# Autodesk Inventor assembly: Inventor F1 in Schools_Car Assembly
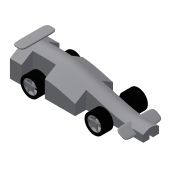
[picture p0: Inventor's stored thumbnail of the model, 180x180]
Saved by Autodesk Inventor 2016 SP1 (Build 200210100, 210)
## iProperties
Category: F1 in Schools
Company: Autodesk Inc.
Created: 2015-12
Part Number: Inventor F1 in Schools_Car Assembly
Document SubType Name: Assembly
Designer: Autodesk Inc.
Author: Autodesk Inc
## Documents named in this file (7)
- D:\F1 2016\F1 Inventor Tutorial\Data Sets\Beginner Do not Edit\Inventor F1 in Schools_CarAssembly.iam
- D:\F1 2016\F1 Inventor Tutorial\Data Sets\Beginner Do not Edit\Inventor F1 in Schools_Wheel.iam
- D:\F1 2016\F1 Inventor Tutorial\Data Sets\Beginner Do not Edit\Inventor F1 in Schools_Axle.ipt
- D:\F1 2016\F1 Inventor Tutorial\Data Sets\Beginner Do not Edit\Inventor F1 in Schools_TestBlock.ipt
- D:\F1 2016\F1 Inventor Tutorial\Data Sets\Beginner Do not Edit\Inventor F1 in Schools_RearWing.ipt
- D:\F1 2016\F1 Inventor Tutorial\Data Sets\Beginner Do not Edit\Inventor F1 in Schools_FrontWing.ipt
- D:\F1 2016\F1 Inventor Tutorial\Data Sets\Beginner Do not Edit\Inventor F1 in Schools_Body.ipt
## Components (10 placed, 6 different names)
1. Inventor F1 in Schools_Body:1 — Flush:1, Flush:2, Flush:3, Mate:1, Flush:4, Mate:2, Flush:5, Mate:4, Flush:7, Mate:7, Flush:10, Flush:11, Mate:9, Flush:12
2. Inventor F1 in Schools_RearWing:1 — Flush:1, Flush:2
3. Inventor F1 in Schools_FrontWing:1 — Flush:3
4. Inventor F1 in Schools_Wheel:1 [sub-assembly] — Mate:5, Flush:7
5. Inventor F1 in Schools_Wheel:2 [sub-assembly] — Mate:3, Mate:4
6. Inventor F1 in Schools_Wheel:3 [sub-assembly] — Mate:8, Flush:10
7. Inventor F1 in Schools_Wheel:4 [sub-assembly] — Mate:6, Mate:7
8. Inventor F1 in Schools_Axle:1 — Mate:1, Flush:4, Mate:3, Mate:5
9. Inventor F1 in Schools_Axle:2 — Mate:2, Flush:5, Mate:6, Mate:8
10. Inventor F1 in Schools_TestBlock — Flush:11, Mate:9, Flush:12
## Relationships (18: Flush 9, Mate 9)
- Flush:1: Inventor F1 in Schools_Body:1 ↔ Inventor F1 in Schools_RearWing:1
- Flush:2: Inventor F1 in Schools_Body:1 ↔ Inventor F1 in Schools_RearWing:1
- Flush:3: Inventor F1 in Schools_Body:1 ↔ Inventor F1 in Schools_FrontWing:1
- Mate:1: Inventor F1 in Schools_Body:1 ↔ Inventor F1 in Schools_Axle:1
- Flush:4: Inventor F1 in Schools_Body:1 ↔ Inventor F1 in Schools_Axle:1
- Mate:2: Inventor F1 in Schools_Body:1 ↔ Inventor F1 in Schools_Axle:2
- Flush:5: Inventor F1 in Schools_Body:1 ↔ Inventor F1 in Schools_Axle:2
- Mate:3: Inventor F1 in Schools_Wheel:2 ↔ Inventor F1 in Schools_Axle:1
- Mate:4: Inventor F1 in Schools_Body:1 ↔ Inventor F1 in Schools_Wheel:2
- Mate:5: Inventor F1 in Schools_Wheel:1 ↔ Inventor F1 in Schools_Axle:1
- Flush:7: Inventor F1 in Schools_Body:1 ↔ Inventor F1 in Schools_Wheel:1
- Mate:6: Inventor F1 in Schools_Wheel:4 ↔ Inventor F1 in Schools_Axle:2
- Mate:7: Inventor F1 in Schools_Body:1 ↔ Inventor F1 in Schools_Wheel:4
- Mate:8: Inventor F1 in Schools_Wheel:3 ↔ Inventor F1 in Schools_Axle:2
- Flush:10: Inventor F1 in Schools_Body:1 ↔ Inventor F1 in Schools_Wheel:3
- Flush:11: Inventor F1 in Schools_Body:1 ↔ Inventor F1 in Schools_TestBlock
- Mate:9: Inventor F1 in Schools_Body:1 ↔ Inventor F1 in Schools_TestBlock
- Flush:12: Inventor F1 in Schools_Body:1 ↔ Inventor F1 in Schools_TestBlock
